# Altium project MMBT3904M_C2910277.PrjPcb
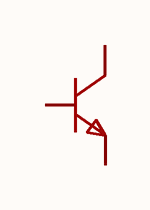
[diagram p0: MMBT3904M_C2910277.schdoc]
1 sheet, 1 parts. Net scope: global (net labels, ports and power ports of the same name join across sheets).

## Sheet MMBT3904M_C2910277.schdoc
size 127 x 101 mm

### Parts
Q?  mmbt3904m_c2910277  [SOT-723_L1.2-W0.8-P0.40-LS1.2-BR]  (value not drawn)

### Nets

Not connected (* = marked no-connect by the designer): Q? 1(B) 2(E) 3(C)

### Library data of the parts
Q? = mmbt3904m_c2910277: 晶体管类型:NPN;集电极电流(Ic):200mA;集射极击穿电压(Vceo):40V;耗散功率(Pd):100mW;直流电流增益(hFE):40;; Manufacturer: CJ(江苏长电/长晶); AddInBom: yes; ModelId: abccde1e67074d7481274a37cf5c97f0; ModelName: SOT-723-3P_L1.2-W0.8-H0.6-LS1.2-P0.40; ModelTransform: 47.244,47.244,0,180,0,0,0,0,0; type: NPN; Current - Collector(Ic): 200mA; Collector - Emitter Voltage VCEO: 40V; Pd - Power Dissipation: 100mW; DC Current Gain: 40; Transition frequency(fT): 300MHz; Current - Collector Cutoff: 50nA; Vce Saturation(VCE(sat)): 300mV; Emitter-Base Voltage(Vebo): 6V; Number: 1个NPN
